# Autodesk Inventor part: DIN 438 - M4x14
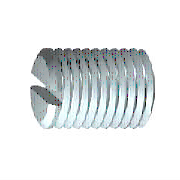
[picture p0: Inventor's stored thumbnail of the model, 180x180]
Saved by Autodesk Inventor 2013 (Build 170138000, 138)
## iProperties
Created: 2012-02
Part Number: DIN 438 - M4x14
Material: Stahl, weich
Description: Gewindestifte mit Schlitz und Ringschneide
Document SubType Name: Modeling
Standard: DIN 438
Designer: Hübner
Standards Organization: DIN
Language: de-DE
Size Designation: M4x14
Categories: <MemberInstance><Categories><Category DisplayName="Verbindungselemente" InternalName="e4da775c-781d-43d5-af7c-5136215cf5a6" Mnemonic="FSTN"><Category DisplayNam
Density: 7.86 g/cm^3
IsCustomPart: 0
Author: Hübner
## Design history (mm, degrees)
sketch "Skizze2"
  geometry: L1 (-0.9, -13.65)-(-2, -12.55); L2 (0, -13.65)-(-0.9, -13.65); L3 (0, 0.35)-(0, -13.65); L4 (-1.65, 0.35)-(0, 0.35); L5 (-2, 0)-(-1.65, 0.35); L6 (-2, -12.55)-(-2, 0); L7 (0, -16.45)-(0, 3.15) reference; L8 (0.4, 0)-(-2.4, 0) reference
  constraints: 12 end point, 2 horizontal, 2 vertical
  dimensions: "d2" = 14 distance of L3.start L2.start (= NLG); "d4" = 0.9 distance of L2.start L1.start (= 0.5 x dp); "d6" = 0.35 horizontal distance of L5.start L4.start (= 0.5 x PTC); "d8" = 0.35 horizontal distance of L5.start L4.start (= 0.5 x PTC); "d10" = 2 horizontal distance of L5.start L3.start (= 0.5 x NND); "d12" = 135 deg angle of L6 L1; "d16" = 0 distance between parallel lines of L7 L3; "d17" = 0 distance from line of L8 L5.start
revolve "Drehung1" sketch "Skizze2" stored, may be unused: angle "d13" = 360 deg
sketch "Skizze5"
  geometry: L1 (0, -13.65)-(-0.9, -13.65); L2 (-0.9, -13.65)-(0, -13.13); L3 (0, -13.13)-(0, -13.65); L4 (0, -16.45)-(0, 3.15) reference; L5 (0.33, 0)-(-1.98, 0) reference; L6 (-0.4, 0.35)-(-1.65, 0.35) reference
  constraints: 6 end point, 1 collinear, 1 horizontal, 1 perpendicular
  dimensions: "d25" = 1.8 diameter of L1.end L3 (= dp); "d27" = 30 deg angle of L2 L1; "d28" = 14 distance between parallel lines of L1 L6 (= NLG)
revolve "Drehung2" sketch "Skizze5" stored, may be unused: angle "d29" = 90 deg
node "MSC_PF1"
node "MSC_A1"
body "Solid1"
sketch "Skizze4"
  geometry: L1 (-0.4, -1.07)-(0.4, -1.07); L2 (0.4, -1.07)-(0.4, 0.35); L3 (0.4, 0.35)-(-0.4, 0.35); L4 (-0.4, 0.35)-(-0.4, -1.07); L5 (0, -1.354)-(0, 0.634) reference; L6 (2.31, 0)-(-2.31, 0) reference; L7 (1.65, 0.35)-(-1.65, 0.35) reference; 1 further point
  constraints: 8 end point, 2 midpoint, 2 parallel, 1 horizontal, 1 perpendicular, 1 point on line
  dimensions: "d18" = 1.42 distance of L1.end L2.end (= ParT); "d19" = 0.8 distance of L2.end L3.end (= ParN)
extrude "Extrusion1" cut sketch "Skizze4" stored distance "d20" = 4 (= NND); taper "d21" = 0 deg
feature "Gewinde1" dims "d22" = 10, "d23" = 0
other parameters: "NND" = 4 [user parameter; used in 3 equation terms], "PTC" = 0.7 [user parameter; used in 2 equation terms], "NLG" = 14 [user parameter; used in 2 equation terms], "dp" = 1.8 [user parameter; used in 2 equation terms], "ParT" = 1.42 [user parameter; used in 1 equation term], "ParN" = 0.8 [user parameter; used in 1 equation term], "d3" = 1 (derived), "d5" = 0.35 (derived), "d7" = 0.35 (derived), "d9" = 2 (derived), "d11" = 135 deg (derived), "d24" = 0, "d31" = 0, "d33" = 0, "THREADDIA" = 4 (= NND) [user parameter]
